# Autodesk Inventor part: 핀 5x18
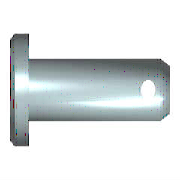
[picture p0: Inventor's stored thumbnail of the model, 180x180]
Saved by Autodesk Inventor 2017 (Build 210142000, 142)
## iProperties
Created: 2012-02
Part Number: 핀 5x18
Material: 강철
Description: 머리가 있는 클레비스 핀
Document SubType Name: Modeling
Standard: ISO 2341
Designer: test
Standard Revision: Second edition 1986-11-01
Standards Organization: ISO
Language: ko-KR
Size Designation: B - 5 x 18
Categories: <MemberInstance><Categories><Category DisplayName="조임쇠" InternalName="e4da775c-781d-43d5-af7c-5136215cf5a6" Mnemonic="FSTN"><Category DisplayName="핀" InternalNa
Density: 7.85 g/cm^3
Appearance: 주황색
IsCustomPart: 1
Author: test
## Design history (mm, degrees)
sketch "스케치1"
  geometry: L1 (-1.6, 0)-(-1.6, 4); L2 (-1.6, 4)-(0, 4); L3 (0, 4)-(0, 2.5); L4 (0, 2.5)-(18, 2.5); L5 (18, 2.5)-(18, 0); L6 (-1.6, 0)-(18, 0); L7 (-4, 0)-(17, 0) reference; L8 (0, -0.98)-(0, 3.08) reference; C1 r 0.6 at (15.1, 0)
  constraints: 12 end point, 3 parallel, 2 collinear, 2 perpendicular, 1 centre point, 1 point on line, 1 vertical
  dimensions: "d0" = 5 diameter of L4 L6 (= NND); "d1" = 8 diameter of L2 L6 (= KOD); "d2" = 1.6 distance of L1.end L2.end (= KOH); "d3" = 18 distance of L3.end L4.end (= NLG); "d5" = 2.9 distance from line of L5 C1.centre (= DIST); "d6" = 1.2 diameter of C1 (= BOR)
revolve "본체" stored, may be unused: angle "d4" = 90 deg
extrude "구멍" cut sketch "스케치1" stored distance "d7" = 5 (= NND); taper "d8" = 0 deg
workaxis "Work Axis1"
workplane "Work Plane1"
body "Solid1"
chamfer "모따기1" distance "d9" = 1 (= PHH2); stored, may be unused: angle "d10" = 45 deg (= FAWI2), second distance "d16" = 1 (= PHH2)
chamfer "모따기2" distance "d11" = 2 (= PHH1); stored, may be unused: angle "d12" = 30 deg (= FAWI1), second distance "d17" = 2 (= PHH1)
other parameters: "PHH1" = 2 [user parameter; used in 2 equation terms], "PHH2" = 1 [user parameter; used in 2 equation terms], "KOD" = 8 [user parameter; used in 1 equation term], "KOH" = 1.6 [user parameter; used in 1 equation term], "NND" = 5 [user parameter; used in 2 equation terms], "FAWI1" = 30 deg [user parameter; used in 1 equation term], "FAWI2" = 45 deg [user parameter; used in 1 equation term], "DIST" = 2.9 [user parameter; used in 1 equation term], "BOR" = 1.2 [user parameter; used in 1 equation term], "NLG" = 18 [user parameter; used in 1 equation term], "d13" = 0, "d14" = 0, "d27" = 0, "d28" = 0, "d29" = 0, "d30" = 0, "d31" = 0
